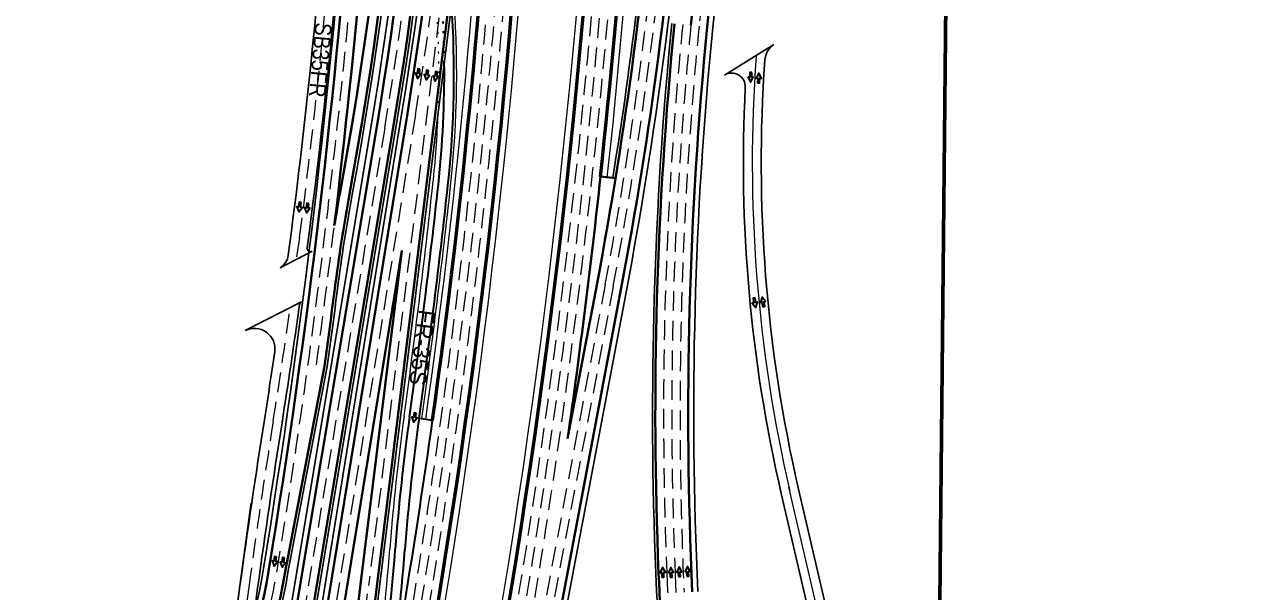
# Model space of a CAD drawing. Extents: x 2329387 to 2347382, y 6951580 to 6987999.
# Drawn here: x 2331270 to 2333058, y 6961800 to 6962627 of the extents above; entities that cross this region are included whole.
import ezdxf

# ---------------------------------------------------------------- set-up
doc = ezdxf.new("R2010")
doc.units = 0
doc.header["$LTSCALE"] = 9.6
doc.linetypes.add('DOTTED', pattern=[1.5, 0.3, -1.2])
doc.linetypes.add('MEDIUM_DASHED', pattern=[4.5, 3, -1.5])
for name, color, linetype, lineweight in [('26', 7, 'Continuous', 53), ('27', 7, 'Continuous', 40), ('28', 7, 'Continuous', 25), ('29', 7, 'DOTTED', 35), ('41', 7, 'Continuous', 35), ('50', 7, 'MEDIUM_DASHED', 13), ('62', 7, 'Continuous', 60), ('63', 7, 'Continuous', 25)]:
    doc.layers.add(name, color=color, linetype=linetype, lineweight=lineweight)
doc.layers.add('40', color=7, linetype='Continuous')

msp = doc.modelspace()

# ---------------------------------------------------------------- linework, layer by layer
at = {"layer": '26'}
for centre, radius, start, end in [((2320619.05, 6963651.709), 11510.156, 348.37024, 3.41668), ((2321018.843, 6963569.511), 11000, 348.37024, 2.99621), ((2320619.05, 6963651.709), 11558.156, 353.8091, 2.18285), ((2321018.843, 6963569.511), 10952, 352.02498, 2.27299)]:
    msp.add_arc(centre, radius, start, end, dxfattribs=at)
at = {"layer": '26', "lineweight": 13}
for centre, radius, start, end in [((2320619.05, 6963651.709), 11500.156, 348.37024, 3.35435), ((2321018.843, 6963569.511), 11010, 348.37024, 3.10741), ((2320619.05, 6963651.709), 11568.156, 353.8091, 2.18285), ((2321018.843, 6963569.511), 10942, 352.02498, 2.03298)]:
    msp.add_arc(centre, radius, start, end, dxfattribs=at)
at = {"layer": '27'}
for p, q in [((2331896.517, 6962721.31), (2331783.536, 6961807.284)), ((2331828.117, 6962497.325), (2331689.483, 6961644.667)), ((2331783.384, 6962478.032), (2331537.705, 6961007.603)), ((2331807.056, 6962474.077), (2331560.779, 6961000.065)), ((2332131.671, 6962402.888), (2332109.8, 6962405.26)), ((2331819.966, 6962297.645), (2331713.172, 6961640.816)), ((2331819.966, 6962297.645), (2331759.718, 6961810.228)), ((2332140.099, 6962242.879), (2331999.406, 6961499.077)), ((2332104.726, 6962249.57), (2332061.896, 6962023.141)), ((2331707.295, 6962128.965), (2331649.989, 6961828.753))]:
    msp.add_line(p, q, dxfattribs=at)
at = {"layer": '27', "lineweight": 25}
for p, q in [((2331900.487, 6962720.82), (2331787.506, 6961806.793)), ((2331820.221, 6962498.609), (2331681.587, 6961645.951)), ((2331775.493, 6962479.35), (2331530.014, 6961010.115)), ((2331811.001, 6962473.417), (2331652.783, 6961526.455)), ((2332147.959, 6962241.392), (2332047.286, 6961709.162)), ((2331711.244, 6962128.317), (2331653.918, 6961828.003))]:
    msp.add_line(p, q, dxfattribs=at)
at = {"layer": '27'}
for centre, radius, start, end in [((2339406.145, 6959556.474), 7976, 170.51466, 170.51466), ((2319783.502, 6963768.598), 11999.998, 350.71583, 0.79832), ((2319783.502, 6963768.598), 12023.998, 353.14789, 0.79832), ((2325765.131, 6963475.29), 6064.174, 349.61744, 0.70842), ((2325765.131, 6963475.29), 6078.174, 349.61744, 0.70842), ((2325865.417, 6963466.803), 6000, 350.51466, 0.68489), ((2325865.417, 6963466.803), 6024, 350.51466, 0.68489), ((2325865.417, 6963466.803), 6041, 350.76507, 0.68489), ((2320644.096, 6963773.403), 11654.156, 354.34987, 357.81948), ((2326209.306, 6963364.708), 5999.959, 349.28886, 355.79988), ((2326209.306, 6963364.708), 6035.959, 349.28886, 355.79988), ((2337955.315, 6962060.73), 5741.578, 171.39088, 174.34987), ((2337955.315, 6962060.73), 5717.578, 171.39088, 174.34987), ((2337955.315, 6962060.73), 5765.578, 174.34987, 182.32731), ((2337955.315, 6962060.73), 5717.578, 174.34987, 182.61584), ((2320619.05, 6963651.709), 11558.156, 351.89995, 353.8091), ((2334321.473, 6961907.6), 2634.599, 169.61744, 170.68479), ((2334321.473, 6961907.6), 2620.599, 169.61744, 172.66731), ((2319783.502, 6963768.598), 12035.998, 352.1704, 352.71353), ((2330886.127, 6961953.624), 750.001, 266.08609, 350.71584), ((2330886.127, 6961953.624), 774.001, 266.08608, 350.71582), ((2337105.762, 6962041.019), 4915.948, 182.49984, 187.6536), ((2325828.855, 6962543.331), 5976, 348.01367, 352.95352), ((2325828.855, 6962543.331), 6000, 348.01367, 352.95352)]:
    msp.add_arc(centre, radius, start, end, dxfattribs=at)
at = {"layer": '27', "lineweight": 25}
for centre, radius, start, end in [((2319783.502, 6963768.598), 11991.998, 350.71583, 0.79832), ((2325765.131, 6963475.29), 6082.174, 349.61744, 0.70842), ((2325865.417, 6963466.803), 5992, 350.51466, 0.68489), ((2325865.417, 6963466.803), 6028, 350.51466, 0.68489), ((2325865.417, 6963466.803), 6033, 350.76507, 0.68489), ((2326209.306, 6963364.708), 5995.959, 350.77341, 355.79988), ((2326209.306, 6963364.708), 6043.959, 349.28886, 355.79988), ((2337955.315, 6962060.73), 5709.578, 171.39088, 174.34987), ((2337955.315, 6962060.73), 5769.578, 174.34987, 182.32731), ((2337955.315, 6962060.73), 5709.578, 174.34987, 182.61584), ((2334321.473, 6961907.6), 2616.599, 169.61744, 172.66731), ((2319783.502, 6963768.598), 12039.998, 352.16991, 352.71353), ((2330886.127, 6961953.624), 742.001, 266.08609, 350.71584), ((2330886.127, 6961953.624), 778.001, 266.08608, 350.71189), ((2336798.354, 6962013.709), 4611.662, 182.32731, 187.46451), ((2325828.855, 6962543.331), 6004, 348.01367, 352.95352)]:
    msp.add_arc(centre, radius, start, end, dxfattribs=at)
at = {"layer": '28'}
for p, q in [((2332290.503, 6962553.424), (2332362.687, 6962597.982)), ((2331642.454, 6962272.418), (2331689.358, 6962296.335)), ((2332428.738, 6961704.35), (2332371.919, 6961949.587)), ((2332398.645, 6961949.425), (2332454.067, 6961710.219))]:
    msp.add_line(p, q, dxfattribs=at)
for centre, radius, start, end in [((2321980.757, 6963571.336), 9784.134, 352.54246, 357.94854), ((2321980.757, 6963571.336), 9758.134, 352.45851, 355.79885), ((2332379.342, 6962573.03), 30, 123.7231, 175.95214), ((2334455.922, 6962426.078), 2111.773, 175.95214, 193.04477), ((2332300.97, 6962536.382), 20, 357.06981, 121.55569), ((2334455.922, 6962426.078), 2137.773, 177.06981, 193.04477), ((2331687.087, 6962300.789), 5, 172.54246, 297.01806), ((2331629.699, 6962293.919), 25, 300.67751, 352.45851)]:
    msp.add_arc(centre, radius, start, end, dxfattribs=at)
at = {"layer": '28', "linetype": 'DOTTED', "lineweight": 13}
msp.add_arc((2330382.082, 6962555.363), 1491.999, 357.81169, 8.34815, dxfattribs=at)
at = {"layer": '28', "lineweight": 13}
for centre, radius, start, end in [((2330382.082, 6962555.363), 1517.999, 353.8183, 4.62003), ((2330382.082, 6962555.363), 1491.999, 353.8183, 357.81169), ((2321018.854, 6963569.51), 10909.989, 352.02497, 353.8183), ((2321018.854, 6963569.51), 10935.989, 352.02497, 353.8183), ((2334802.242, 6961638.507), 3008.005, 172.02497, 175.72896), ((2328818.901, 6962085.355), 2991.998, 351.68506, 355.72896)]:
    msp.add_arc(centre, radius, start, end, dxfattribs=at)
at = {"layer": '29', "linetype": 'Continuous'}
msp.add_line((2331845.116, 6962052.79), (2331864.922, 6962050.015), dxfattribs=at)
at = {"layer": '29'}
msp.add_arc((2330382.082, 6962555.363), 1499.999, 0.60632, 9.46235, dxfattribs=at)
at = {"layer": '29', "linetype": 'Continuous'}
for centre, radius, start, end in [((2330382.082, 6962555.363), 1513.999, 353.8183, 3.86264), ((2330382.082, 6962555.363), 1499.999, 353.8183, 0.60632), ((2321018.854, 6963569.51), 10917.989, 352.02497, 353.8183), ((2321018.854, 6963569.51), 10931.989, 352.02497, 353.8183), ((2321018.843, 6963569.511), 10952, 349.90135, 352.02498), ((2334802.242, 6961638.507), 3000.005, 172.02497, 175.72896), ((2334802.242, 6961638.507), 2986.005, 172.02497, 175.72896), ((2328818.901, 6962085.355), 2999.998, 349.22683, 355.72896), ((2328818.901, 6962085.355), 3013.998, 351.67854, 355.72896)]:
    msp.add_arc(centre, radius, start, end, dxfattribs=at)
at = {"layer": '41'}
for points in [[(2331846.516, 6962562.094), (2331843.542, 6962562.498), (2331842.626, 6962555.753), (2331840.211, 6962556.081), (2331842.985, 6962548.438), (2331847.699, 6962555.064), (2331845.599, 6962555.349)], [(2331859.073, 6962560.071), (2331856.099, 6962560.475), (2331855.183, 6962553.73), (2331852.767, 6962554.059), (2331855.542, 6962546.415), (2331860.256, 6962553.041), (2331858.156, 6962553.326)], [(2331871.908, 6962558.349), (2331868.935, 6962558.753), (2331868.018, 6962552.008), (2331865.603, 6962552.336), (2331868.378, 6962544.693), (2331873.092, 6962551.319), (2331870.991, 6962551.604)], [(2332330.621, 6962557.115), (2332327.621, 6962557.191), (2332327.451, 6962550.386), (2332325.014, 6962550.447), (2332328.611, 6962543.154), (2332332.569, 6962550.258), (2332330.45, 6962550.311)], [(2332338.865, 6962542.065), (2332341.864, 6962541.99), (2332342.035, 6962548.794), (2332344.471, 6962548.733), (2332340.874, 6962556.026), (2332336.916, 6962548.923), (2332339.035, 6962548.87)], [(2331673.143, 6962367.486), (2331670.16, 6962367.817), (2331669.41, 6962361.051), (2331666.987, 6962361.32), (2331669.949, 6962353.747), (2331674.499, 6962360.487), (2331672.392, 6962360.721)], [(2331684.378, 6962366.133), (2331681.396, 6962366.464), (2331680.645, 6962359.699), (2331678.223, 6962359.967), (2331681.184, 6962352.394), (2331685.734, 6962359.134), (2331683.627, 6962359.368)], [(2332335.222, 6962228.501), (2332332.278, 6962227.924), (2332333.588, 6962221.244), (2332331.196, 6962220.775), (2332336.29, 6962214.437), (2332338.612, 6962222.23), (2332336.533, 6962221.822)], [(2332346.536, 6962215.598), (2332349.48, 6962216.176), (2332348.17, 6962222.855), (2332350.562, 6962223.325), (2332345.467, 6962229.663), (2332343.145, 6962221.87), (2332345.225, 6962222.278)], [(2331841.198, 6962060.494), (2331838.236, 6962060.975), (2331837.145, 6962054.256), (2331834.739, 6962054.647), (2331837.315, 6962046.934), (2331842.199, 6962053.436), (2331840.107, 6962053.775)], [(2331637.363, 6961850.921), (2331634.389, 6961851.321), (2331633.483, 6961844.575), (2331631.067, 6961844.899), (2331633.854, 6961837.26), (2331638.558, 6961843.893), (2331636.457, 6961844.175)], [(2331648.904, 6961849.135), (2331645.93, 6961849.535), (2331645.024, 6961842.789), (2331642.608, 6961843.113), (2331645.395, 6961835.474), (2331650.098, 6961842.107), (2331647.998, 6961842.389)], [(2332199.291, 6961821.103), (2332202.288, 6961821.243), (2332201.971, 6961828.043), (2332204.406, 6961828.156), (2332200.296, 6961835.172), (2332196.857, 6961827.804), (2332198.974, 6961827.903)], [(2332211.286, 6961821.139), (2332214.284, 6961821.279), (2332213.967, 6961828.079), (2332216.401, 6961828.192), (2332212.291, 6961835.208), (2332208.852, 6961827.84), (2332210.969, 6961827.939)], [(2332223.405, 6961821.815), (2332226.403, 6961821.955), (2332226.086, 6961828.754), (2332228.52, 6961828.868), (2332224.41, 6961835.884), (2332220.971, 6961828.516), (2332223.088, 6961828.614)], [(2332235.534, 6961822.582), (2332238.532, 6961822.722), (2332238.215, 6961829.521), (2332240.65, 6961829.635), (2332236.54, 6961836.651), (2332233.1, 6961829.283), (2332235.217, 6961829.382)]]:
    msp.add_lwpolyline(points, close=True, dxfattribs=at)
at = {"layer": '50'}
for p, q in [((2331884.608, 6962722.782), (2331771.627, 6961808.756)), ((2331839.962, 6962495.399), (2331701.328, 6961642.742)), ((2331795.22, 6962476.054), (2331549.242, 6961003.834)), ((2331670.997, 6962316.628), (2331665.906, 6962284.376)), ((2332116.517, 6962247.339), (2331975.824, 6961503.538)), ((2332128.308, 6962245.109), (2331987.615, 6961501.307))]:
    msp.add_line(p, q, dxfattribs=at)
at = {"layer": '50', "linetype": 'Continuous'}
msp.add_line((2332441.403, 6961707.284), (2332384.584, 6961952.521), dxfattribs=at)
at = {"layer": '50'}
for centre, radius, start, end in [((2320619.05, 6963651.709), 11546.156, 348.37024, 3.62206), ((2320619.05, 6963651.709), 11522.156, 348.37024, 3.48829), ((2320619.05, 6963651.709), 11534.156, 348.37024, 3.55667), ((2321018.843, 6963569.511), 10988, 348.34293, 2.85027), ((2321018.843, 6963569.511), 10976, 348.37024, 2.68674), ((2321018.843, 6963569.511), 10964, 348.37024, 2.49877), ((2319783.502, 6963768.598), 12011.998, 350.71583, 0.79832), ((2321980.757, 6963571.336), 9771.134, 352.6223, 0.51494), ((2325865.417, 6963466.803), 6012, 350.51466, 0.68489), ((2325865.417, 6963466.803), 6053, 350.76507, 0.68489), ((2326209.306, 6963364.708), 6011.959, 349.28886, 355.79988), ((2326209.306, 6963364.708), 6023.959, 349.28886, 355.79988), ((2337955.315, 6962060.73), 5729.578, 171.39088, 174.34987), ((2337955.315, 6962060.73), 5753.578, 174.34987, 182.32731), ((2337955.315, 6962060.73), 5741.578, 174.34987, 182.32731), ((2337955.315, 6962060.73), 5729.578, 174.34987, 182.61584), ((2319783.502, 6963768.598), 12023.998, 352.1704, 353.14789), ((2330886.127, 6961953.624), 762.001, 266.08609, 350.71584), ((2336798.354, 6962013.709), 4595.662, 182.32731, 192.91301), ((2336798.354, 6962013.709), 4583.662, 182.32731, 182.68873), ((2325828.855, 6962543.331), 5988, 348.01367, 352.95352)]:
    msp.add_arc(centre, radius, start, end, dxfattribs=at)
at = {"layer": '50', "linetype": 'Continuous'}
msp.add_arc((2334455.922, 6962426.078), 2124.773, 175.81786, 193.04477, dxfattribs=at)
at = {"layer": '62'}
msp.add_lwpolyline([(2332642.295, 6965522.154), (2332560.849, 6957416.973), (2330660.943, 6957436.065), (2330739.467, 6965250.394)], close=True, dxfattribs=at)
at = {"layer": '63'}
for p, q in [((2331591.542, 6962180.796), (2331673.628, 6962222.727)), ((2331584.072, 6961808.298), (2331562.27, 6961648.016)), ((2331609.834, 6961804.794), (2331605.162, 6961770.444))]:
    msp.add_line(p, q, dxfattribs=at)
at = {"layer": '63', "lineweight": 13}
msp.add_line((2331584.072, 6961808.298), (2331600.565, 6961929.559), dxfattribs=at)
at = {"layer": '63', "linetype": 'MEDIUM_DASHED', "lineweight": 13}
msp.add_line((2331596.953, 6961806.546), (2331581.886, 6961695.777), dxfattribs=at)
for centre, radius, start, end in [((2321980.757, 6963571.336), 9771.134, 351.03338, 352.01705), ((2342964.284, 6960260.4), 11472, 171.03337, 172.25436)]:
    msp.add_arc(centre, radius, start, end, dxfattribs=at)
at = {"layer": '63'}
for centre, radius, start, end in [((2321980.757, 6963571.336), 9784.134, 351.03337, 352.05518), ((2331675.931, 6962218.289), 5, 117.41929, 172.05518), ((2331605.092, 6962154.03), 30, 351.62268, 116.84929), ((2321980.757, 6963571.336), 9758.134, 351.03337, 351.62268), ((2342964.284, 6960260.4), 11485, 171.03337, 172.25436), ((2342964.284, 6960260.4), 11459, 171.03337, 172.25436)]:
    msp.add_arc(centre, radius, start, end, dxfattribs=at)

# ---------------------------------------------------------------- texts
at = {"layer": '40', "width": 0.9}
msp.add_text('SB35FR', height=24, rotation=264.862, dxfattribs=at).set_placement((2331694.163, 6962630.81))
at = {"layer": '40'}
msp.add_text('FR-35S', height=24, rotation=262.565, dxfattribs=at).set_placement((2331845.076, 6962212.284))

doc.saveas('drawing.dxf')
